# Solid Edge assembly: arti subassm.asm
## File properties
Author: Robert a Rhodes jr
Template: Normal.asm
Last saved by: CADCIM
Revision: 18
Application: Solid Edge
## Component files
rod bush lower.par
rod bush upper.par
articulated rod.par
piston.par
piston pin.par
piston pin plug.par
piston ring.par
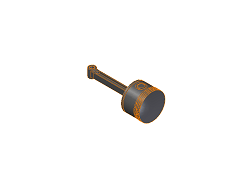
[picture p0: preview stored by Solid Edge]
